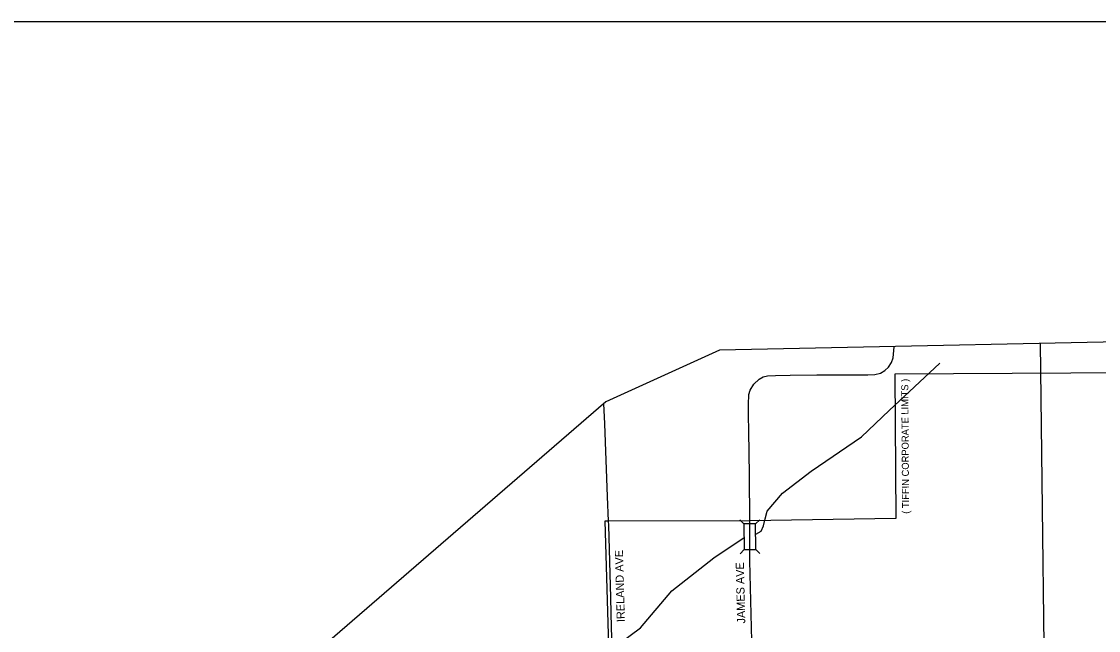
# Model space of a CAD drawing. Extents: x 281.94 to 289.14, y 116.09 to 120.89.
# Drawn here: x 282.9 to 284.748, y 119.742 to 120.787 of the extents above; entities that cross this region are included whole.
import ezdxf

# ---------------------------------------------------------------- set-up
doc = ezdxf.new("R2010")
doc.units = 0
for name, color, linetype in [('tdCiCityStreetCL', 7, 'Continuous'), ('tdCiCityStreetTxt', 7, 'Continuous'), ('tdCiCorpBndry', 7, 'Continuous'), ('tdCiCorpBndryPart', 7, 'Continuous'), ('tdCiCorpBndryTxt', 7, 'Continuous'), ('tdCiHydroRiver', 7, 'Continuous'), ('tdCiMapFrame', 7, 'Continuous'), ('tdCiMapPltShpe', 7, 'Continuous'), ('tdCiSecCL', 7, 'Continuous'), ('tdCiSectLine', 7, 'Continuous'), ('tdCiStrucDataMuni', 7, 'Continuous')]:
    doc.layers.add(name, color=color, linetype=linetype)

msp = doc.modelspace()

# ---------------------------------------------------------------- linework, layer by layer
at = {"layer": 'tdCiCityStreetCL'}
for points in [[(283.9407, 119.6776), (283.931, 119.6886), (283.9223, 119.6988), (283.9181, 119.7057), (283.9167, 119.7097), (283.9147, 119.715), (283.9132, 119.7249), (283.913, 119.7302), (283.9125, 119.7466), (283.9115, 119.7976), (283.9078, 119.9225), (283.9075, 119.9292)], [(284.1542, 119.6796), (284.1537, 119.7013), (284.1499, 119.8612), (284.1497, 119.9065), (284.1497, 119.9085), (284.1497, 119.9217), (284.1496, 119.9302)]]:
    msp.add_lwpolyline(points, dxfattribs=at)
at = {"layer": 'tdCiCorpBndry'}
msp.add_lwpolyline([(284.9013, 120.1845), (284.3984, 120.1814), (284.4003, 119.9337), (284.1496, 119.9302), (283.9074, 119.9294), (283.901, 119.9293), (283.9085, 119.6773)], dxfattribs=at)
at = {"layer": 'tdCiCorpBndryPart'}
msp.add_lwpolyline([(285.1583, 119.9334), (285.1581, 119.939), (284.9038, 119.9359), (284.9013, 120.1845), (284.3984, 120.1814), (284.4003, 119.9337), (284.1496, 119.9302), (283.9074, 119.9294), (283.901, 119.9293), (283.9085, 119.6773), (283.9409, 119.6776), (284.1542, 119.6796)], dxfattribs=at)
at = {"layer": 'tdCiHydroRiver'}
for points in [[(284.1597, 119.9073), (284.1691, 119.912), (284.1731, 119.9212), (284.1757, 119.9336), (284.1796, 119.9467), (284.2058, 119.9774), (284.2549, 120.0154), (284.3412, 120.0743), (284.3884, 120.1194), (284.4754, 120.2006)], [(283.9242, 119.718), (283.9624, 119.7465), (284.016, 119.8099), (284.088, 119.8662), (284.1398, 119.9011)]]:
    msp.add_lwpolyline(points, dxfattribs=at)
at = {"layer": 'tdCiMapFrame'}
msp.add_lwpolyline([(289.038, 120.7868), (289.038, 116.1868), (282.038, 116.1868), (282.038, 120.7868), (289.038, 120.7868)], dxfattribs=at)
at = {"layer": 'tdCiMapPltShpe'}
for points in [[(285.2807, 120.1078), (285.1574, 120.1326), (284.9751, 120.2412), (284.0977, 120.2226)], [(284.0977, 120.2226), (283.9029, 120.1339), (283.1548, 119.4871)]]:
    msp.add_lwpolyline(points, dxfattribs=at)
at = {"layer": 'tdCiSecCL'}
for points in [[(284.1496, 119.9302), (284.149, 120.0081), (284.1481, 120.0845), (284.1475, 120.1109), (284.1471, 120.1293), (284.1481, 120.1467), (284.1503, 120.1541), (284.1565, 120.1647), (284.1658, 120.1731), (284.1723, 120.1768), (284.1801, 120.1787), (284.1934, 120.1796), (284.2186, 120.1799), (284.2645, 120.1802), (284.3518, 120.1802), (284.3642, 120.1811), (284.3739, 120.1836), (284.3813, 120.188), (284.3875, 120.1939), (284.3928, 120.2016), (284.3956, 120.2097), (284.3972, 120.2287), (284.3972, 120.229)], [(283.9075, 119.9292), (283.9053, 119.9717), (283.9009, 120.0963), (283.8995, 120.131)]]:
    msp.add_lwpolyline(points, dxfattribs=at)
at = {"layer": 'tdCiSectLine'}
msp.add_lwpolyline([(284.7005, 117.6247), (284.6788, 118.4309), (284.6579, 119.4326), (284.6484, 120.235)], dxfattribs=at)
at = {"layer": 'tdCiStrucDataMuni'}
for points in [[(284.1596, 119.9246), (284.1496, 119.9246), (284.1396, 119.9245), (284.1325, 119.9316)], [(284.1396, 119.9245), (284.1398, 119.8805), (284.1328, 119.8734)], [(284.1598, 119.8806), (284.1596, 119.9246), (284.1667, 119.9317)], [(284.1398, 119.8805), (284.1498, 119.8806), (284.1598, 119.8806), (284.167, 119.8736)]]:
    msp.add_lwpolyline(points, dxfattribs=at)

# ---------------------------------------------------------------- texts
at = {"layer": 'tdCiCityStreetTxt'}
for s, rotation, p in [('IRELAND AVE', 91.5018, (283.9353, 119.7563)), ('JAMES AVE', 91.3601, (284.1419, 119.7539))]:
    msp.add_text(s, height=0.014, rotation=rotation, dxfattribs=at).set_placement(p)
at = {"layer": 'tdCiCorpBndryTxt'}
msp.add_text('( TIFFIN CORPORATE LIMITS )', height=0.012, rotation=90.3941, dxfattribs=at).set_placement((284.4229, 119.942))

doc.saveas('drawing.dxf')
